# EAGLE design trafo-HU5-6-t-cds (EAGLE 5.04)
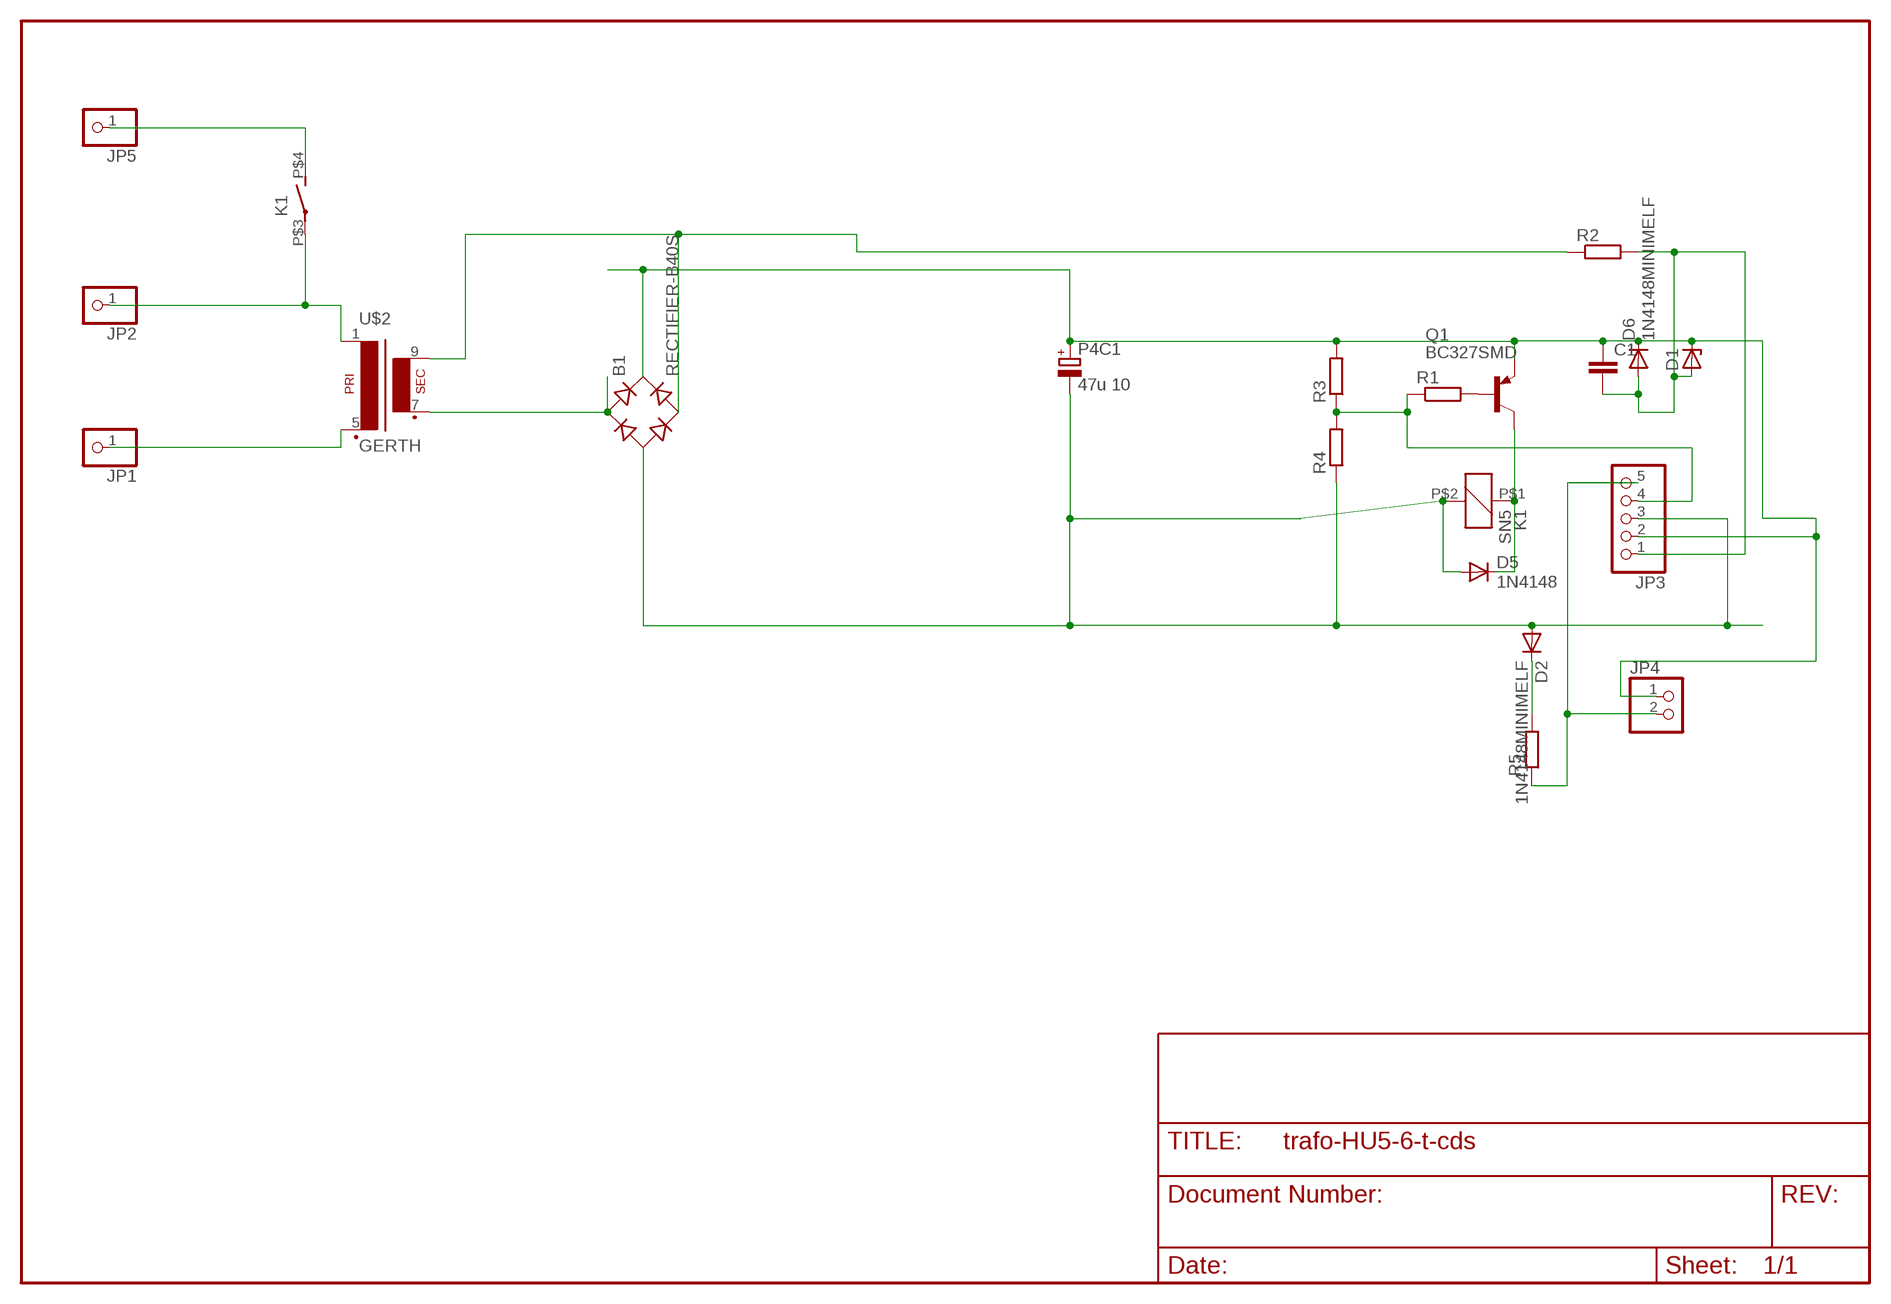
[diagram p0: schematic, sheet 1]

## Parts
B1  RECTIFIER-B40S  [B40S]
C1  C-EUC0805  [C0805]
D1  ZENER-DIODESOT23  [SOT23]
D2  1N4148MINIMELF  [MINIMELF]
D5  1N4148  1N4148MINIMELF  [MINIMELF]
D6  1N4148MINIMELF  [MINIMELF]
JP1  PINHD-1X1  [1X01]
JP2  PINHD-1X1  [1X01]
JP3  PINHD-1X5  [1X05]
JP4  PINHD-1X2  [1X02]
JP5  PINHD-1X1  [1X01]
K1  SN5  [HU]
P4C1  47u 10  CPOL-EUE2-5  [E2-5]
Q1  BC327SMD  [SOT23-BEC]
R1  R-EU_R0805  [R0805]
R2  R-EU_R0805  [R0805]
R3  R-EU_R0805  [R0805]
R4  R-EU_R0805  [R0805]
R5  R-EU_R0805  [R0805]
U$2  GERTH  [150.06]

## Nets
N$1: JP2.1 K1.P$3(2:P) U$2.1
N$2: B1.+ C1.1 D1.3(C) D6.C JP3.2 JP4.1 P4C1.+ Q1.E R3.2
N$3: B1.- D2.A D5.A JP3.3 K1.P$2 P4C1.- R4.1
N$4: JP5.1 K1.P$4(2:S)
N$5: JP1.1 U$2.5(P2)
N$6: B1.AC1 U$2.7(S3)
N$7: B1.AC2 R2.1 U$2.9(S4)
N$8: Q1.B R1.2
N$9: C1.2 D1.1(A) D6.A JP3.1 R2.2
N$10: JP3.4 R1.1 R3.1 R4.2
N$11: D5.C K1.P$1 Q1.C
N$12: JP3.5 JP4.2 R5.1
N$13: D2.C R5.2

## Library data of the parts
B1 = rectifier:RECTIFIER-: Rectifier
C1 = rcl-2:C-EU: CAPACITOR, European symbol
D1 = diode-1:ZENER-DIODE: Z-Diode
D2 D5 D6 = diode-1:1N4148: DIODE
JP1 JP2 JP5 = pinhead(2):PINHD-1X1: PIN HEADER
JP3 = pinhead:PINHD-1X5: PIN HEADER
JP4 = pinhead:PINHD-1X2: PIN HEADER
K1 = relay:SN*: Slim PCB Relay 1 pole 6 A SCHRACK Source: http://www.schrack.com/.. 5815.pdf
P4C1 = rcl:CPOL-EU: POLARIZED CAPACITOR, European symbol
Q1 = transistor-pnp:BC327*: PNP Transistror
R1-R5 = rcl-2:R-EU_: RESISTOR, European symbol
U$2 = trafo:GERTH

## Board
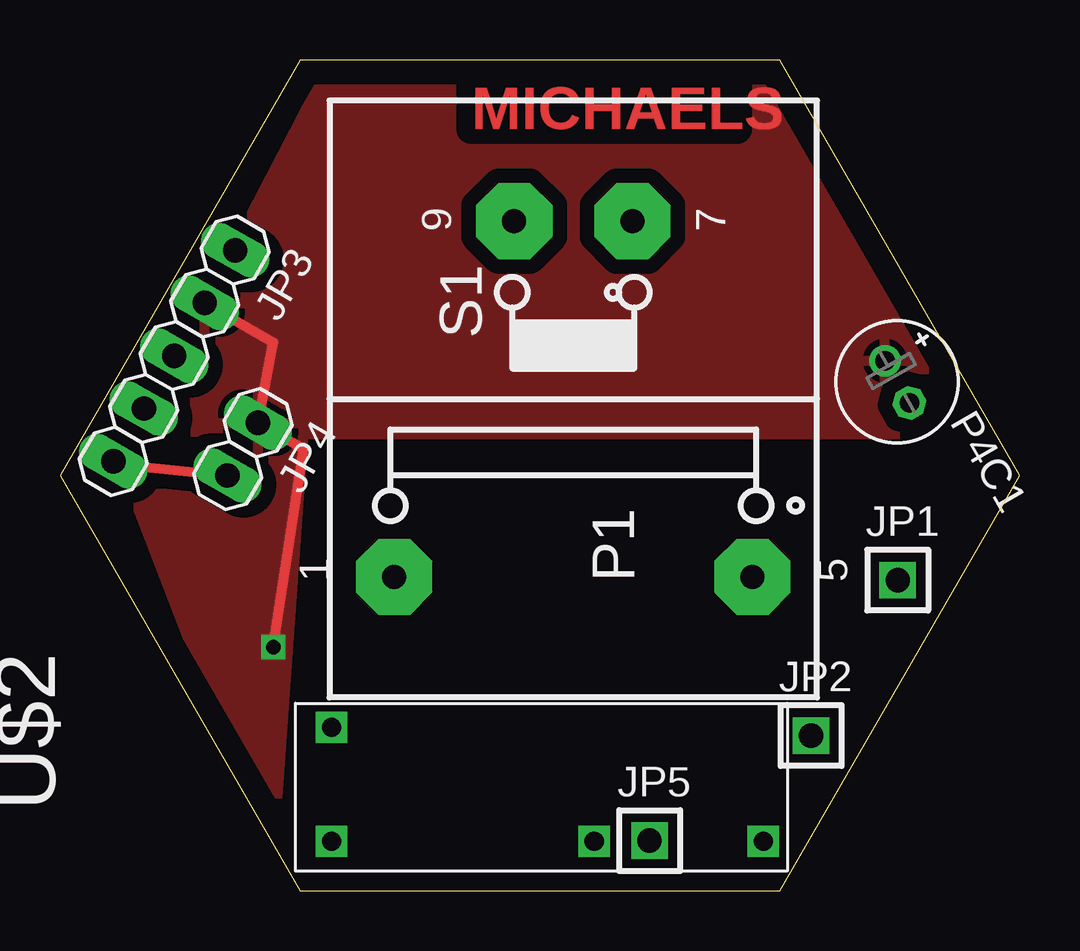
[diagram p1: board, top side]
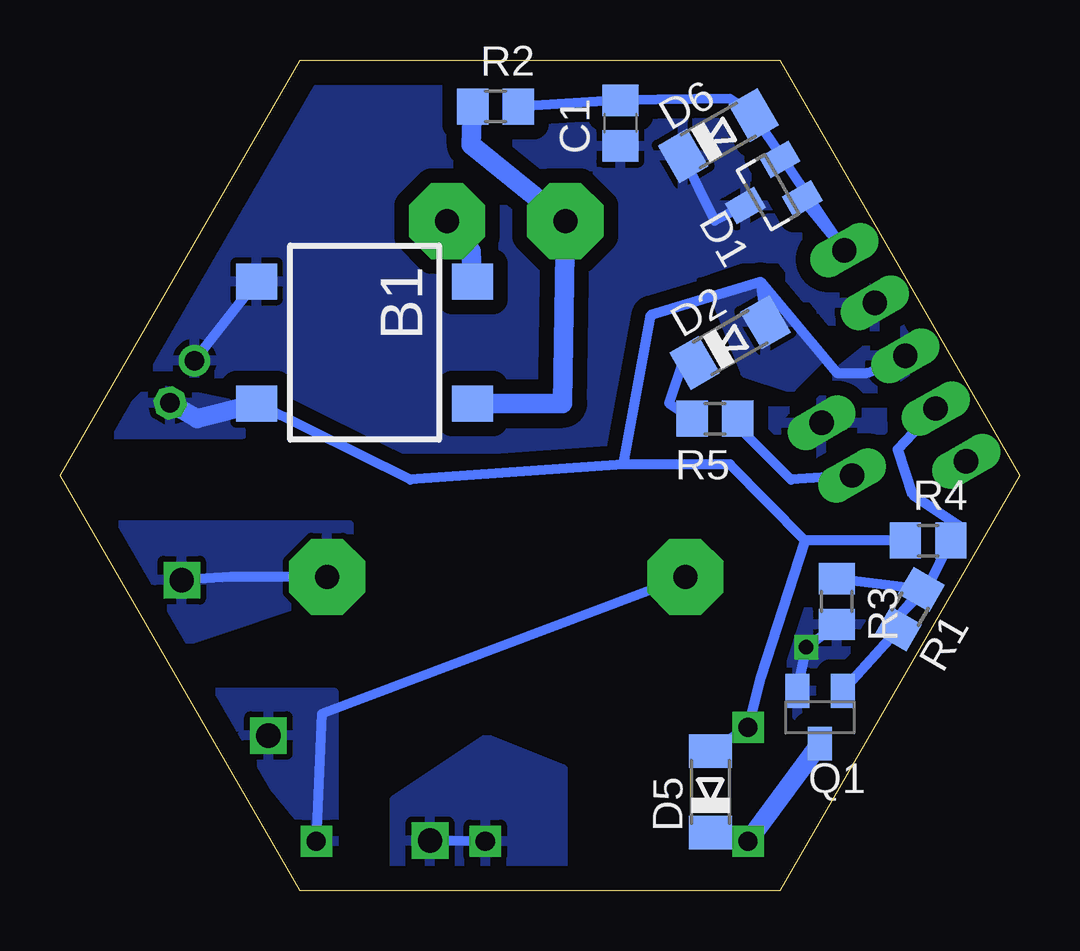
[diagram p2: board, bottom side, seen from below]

Size 40 x 34.64 mm. Coordinates in mm from the lower left corner, seen from the top.
Outline: 10,0 30,0 40,17.32 30,34.64 10,34.64 0,17.32 10,0
Copper layers (1*16): Top 0.035mm / dielectric 1.5mm / Bottom 0.035mm
Design rules "default": minimum track width 10mil, minimum drill 24mil, track to track 8mil, track to pad 8mil, pad to pad 8mil, via to via 8mil, smd to smd 8mil, copper to edge 40mil, drill to drill 8mil, minimum pad ring 10mil, minimum via ring 8mil, stop-mask expansion 4mil, vias tented up to drill 0mil, thermal gap 10mil

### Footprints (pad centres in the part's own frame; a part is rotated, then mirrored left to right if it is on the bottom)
B40S = smd 1.5 x 1.7: + -2.55,-4.5; - 2.55,-4.5; AC1 -2.55,4.5; AC2 2.55,4.5
C0805 = smd 1.3 x 1.5: 1 -0.95,0; 2 0.95,0
SOT23 = smd 1 x 1.4: 1 -0.95,-1.1; 2 0.95,-1.1; 3 0,1.1
MINIMELF = smd 1.4 x 1.8: A 1.7,0; C -1.7,0
1X01 = drill 1.016 square: 1 0,0
1X05 = drill 1.016 long: 1 -5.08,0; 2 -2.54,0; 3 0,0; 4 2.54,0; 5 5.08,0
1X02 = drill 1.016 long: 1 -1.27,0; 2 1.27,0
HU = drill 0.8 square: P$1 2.25,-9; P$2 -2.5,-9; P$3 2.25,9; P$4 2.25,1.95
E2-5 = drill 0.813 pad 1.27 round: + -1.016,0 | drill 0.813 pad 1.27 octagon: - 1.016,0
SOT23-BEC = smd 1 x 1.4: B -0.95,-1.1; C 0,1.1; E 0.95,-1.1
R0805 = smd 1.3 x 1.5: 1 -0.95,0; 2 0.95,0
150.06 = drill 1 pad 3.175 octagon: 1 -7.417,7.468; 5 -7.417,-7.468; 7 7.417,-2.464; 9 7.417,2.464

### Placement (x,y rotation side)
B1  27.3,22.86 270 bottom
C1  16.64,32 90 bottom
D1  10.48,29.12 120 bottom
D2  12.06,22.86 30 bottom
D5  12.89,4.13 90 bottom
D6  12.55,31.49 30 bottom
JP1  34.92,12.95 0 top
JP2  31.31,6.48 0 top
JP3  4.76,22.31 240 top
JP4  7.62,18.41 240 top
JP5  24.57,2.1 0 top
K1  20.32,4.32 270 top
P4C1  34.9,21.22 300 top
Q1  8.32,7.24 180 bottom
R1  4.56,11.75 240 bottom
R2  21.84,32.7 0 bottom
R3  7.62,12.06 270 bottom
R4  3.81,14.61 0 bottom
R5  12.7,19.68 180 bottom
U$2  21.4,20.51 90 top

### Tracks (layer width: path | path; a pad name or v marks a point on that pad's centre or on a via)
N$1
  Bottom 0.406: U$2.1 29.09,7.38 K1.P$3
  pour Bottom (isolate 0.61, rank 2): 28.57,1.27 28.57,8.26 34.29,8.26
N$2  (via drill 0.6)
  Top 0.406: v8.89,10.16 10.16,18.41 JP4.1 8.89,22.86 JP3.2
  Bottom 0.406: P4C1.+ B1.+ | Q1.E v8.89,10.16 R3.2 | D1.3 12.7,27.94 D6.C
  pour Top (isolate 0.61, rank 3): 2.54,17.78 8.89,1.27 10.16,19.05 38.1,19.05 29.21,33.66 10.79,33.66
  pour Bottom (isolate 0.61, rank 3): 2.54,17.78 8.89,1.27 10.16,18.41 38.1,18.41 29.21,33.66 10.79,33.66
N$3
  Bottom 0.406: 16.51,17.78 15.36,24.02 10.79,25.4 | B1.- 25.4,17.14 16.51,17.78 | 8.94,14.6 10.79,8.89 K1.P$2 D5.A | R4.1 8.94,14.6 | JP3.3 6.35,21.59 7.62,21.59 10.79,25.4 | 8.94,14.6 12.06,17.78 16.51,17.78 | 10.79,25.4 D2.A
  Bottom 0.813: B1.- 34.29,19.68 P4C1.-
  pour Bottom (isolate 0.305): 33.02,20.32 36.2,20.95 38.1,19.05 32.38,19.05
  pour Bottom (isolate 0.61, rank 2): 4.45,24.13 7.62,21.59 7.62,20.95 5.71,20.95 3.81,22.23
  pour Bottom: 10.79,25.4 12.7,24.77 11.43,21.59 9.53,20.95 8.26,22.23
N$4
  Bottom 0.406: K1.P$4 JP5.1
  pour Bottom: 26.04,0.64 26.04,3.81 22.23,6.35 19.05,5.08 19.05,0.64
N$5
  Bottom 0.406: U$2.5 32.88,13.09 JP1.1
  pour Bottom (isolate 0.61, rank 2): 27.94,15.24 38.1,15.24 35.56,10.16 27.94,12.7
N$6
  Bottom 0.813: B1.AC1 22.86,26.67 U$2.7
N$7
  Bottom 0.813: R2.1 22.86,31.11 U$2.9 19.05,20.32 B1.AC2
N$8
  Bottom 0.406: R1.2 Q1.B
N$9
  Bottom 0.406: R2.2 C1.2 12.06,33.02 D6.A JP3.1 D1.1
N$10
  Bottom 0.406: JP3.4 5.08,18.41 4.45,16.51 2.54,15.24 3.81,12.7 | 3.81,12.7 5.08,11.43 R1.1 R3.1 | 3.81,12.7 R4.2
N$11
  Bottom 0.406: K1.P$1 D5.C
  Bottom 0.813: K1.P$1 Q1.C
N$12
  Top 0.406: JP4.2 2.54,17.78 JP3.5
  Bottom 0.406: JP4.2 9.53,17.14 11.43,19.05 R5.1
N$13
  Bottom 0.406: R5.2 14.61,20.32 13.97,22.23 D2.C

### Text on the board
Top: MICHAELS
